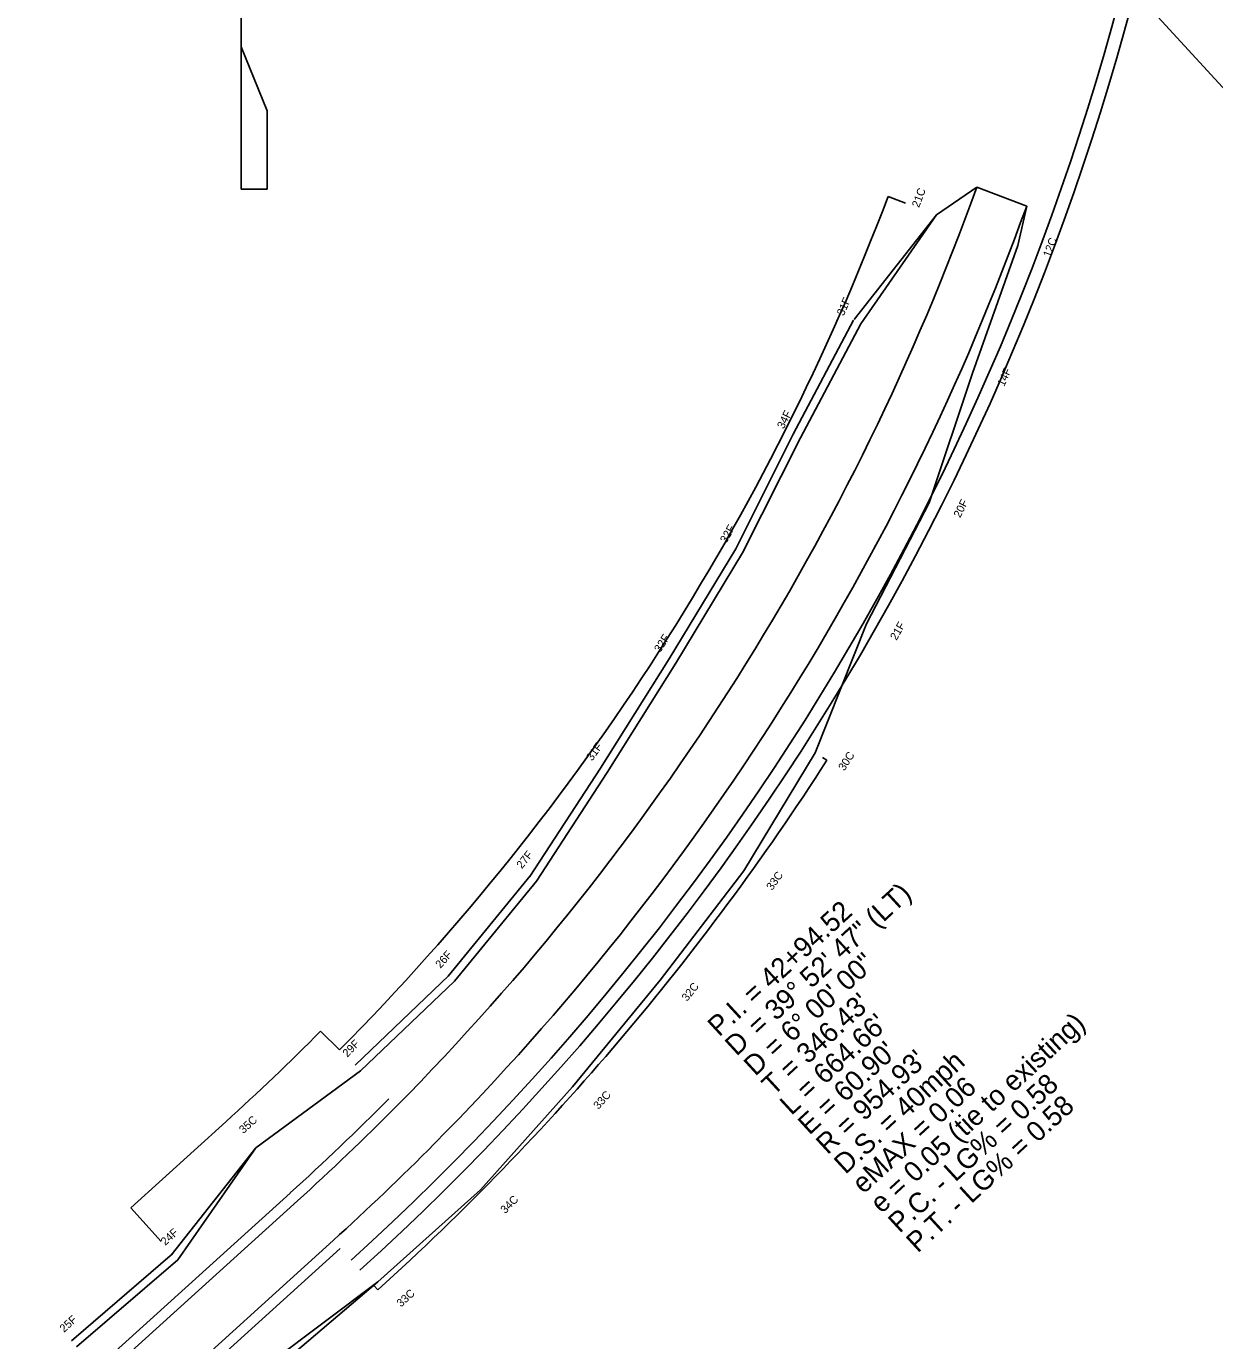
# Model space of a CAD drawing. Extents: x 2116464 to 2118397, y 979599 to 981222.
# Drawn here: x 2117628.4 to 2118074.1, y 980451.6 to 980944.4 of the extents above; entities that cross this region are included whole.
import ezdxf

# ---------------------------------------------------------------- set-up
doc = ezdxf.new("R2010")
doc.units = 0
for name, color, linetype in [('BR_GROUND LINES', 7, 'Continuous'), ('RD_EX_Misc', 7, 'Continuous'), ('RD_PD_CstnLmt', 7, 'Continuous'), ('RD_PD_CstnLmt_TX', 7, 'Continuous'), ('RD_PD_DR_ErosCtrl', 7, 'Continuous'), ('RD_PD_Final_TrvlWay', 7, 'Continuous'), ('RD_PD_GR', 7, 'Continuous'), ('RD_PD_RW', 7, 'Continuous'), ('RD_Sketch2', 7, 'Continuous')]:
    doc.layers.add(name, color=color, linetype=linetype)

msp = doc.modelspace()

# ---------------------------------------------------------------- linework, layer by layer
at = {"layer": 'RD_EX_Misc'}
for p, q in [((2117708.94, 980936.72), (2117708.94, 980991.12)), ((2117718.74, 980912.72), (2117708.94, 980936.72)), ((2117708.94, 980936.72), (2117708.94, 980883.31)), ((2117718.74, 980883.31), (2117718.74, 980912.99)), ((2117718.74, 980912.99), (2117718.74, 980912.72)), ((2117708.94, 980883.31), (2117718.74, 980883.31))]:
    msp.add_line(p, q, dxfattribs=at)
at = {"layer": 'RD_PD_CstnLmt'}
for p, q in [((2117969.75, 980873.73), (2117984.88, 980884.04)), ((2118000.26, 980862.18), (2118003.59, 980876.96)), ((2117941.36, 980832.8), (2117969.75, 980873.73)), ((2117983.25, 980814.38), (2118000.26, 980862.18)), ((2117918.71, 980790.09), (2117941.36, 980832.8)), ((2117967.03, 980765.75), (2117983.25, 980814.38)), ((2117897.04, 980746.94), (2117918.71, 980790.09)), ((2117943.47, 980720.42), (2117967.03, 980765.75)), ((2117872.03, 980705.62), (2117897.04, 980746.94)), ((2117924.27, 980672.04), (2117943.47, 980720.42)), ((2117846.31, 980664.65), (2117872.03, 980705.62)), ((2117897.55, 980627.77), (2117924.27, 980672.04)), ((2117819.75, 980623.93), (2117846.31, 980664.65)), ((2117866.1, 980586.74), (2117897.55, 980627.77)), ((2117788.97, 980586.31), (2117819.75, 980623.93)), ((2117753.78, 980552.75), (2117788.97, 980586.31)), ((2117833.3, 980546.76), (2117866.1, 980586.74)), ((2117714.55, 980523.86), (2117753.78, 980552.75)), ((2117798.79, 980508.16), (2117833.3, 980546.76)), ((2117685.2, 980481.88), (2117714.55, 980523.86)), ((2117760.21, 980473.62), (2117798.79, 980508.16)), ((2117647.26, 980449.29), (2117685.2, 980481.88)), ((2117720.02, 980443.41), (2117760.21, 980473.62))]:
    msp.add_line(p, q, dxfattribs=at)
for radius in [974.93, 979.93]:
    msp.add_arc((2117095.97, 981204.56), radius, 312.14821, 352.02781, dxfattribs=at)
at = {"layer": 'RD_PD_DR_ErosCtrl'}
for p, q in [((2117938.89, 980834.51), (2117969.75, 980873.73)), ((2117916.06, 980791.5), (2117938.7, 980834.21)), ((2117894.36, 980748.29), (2117916.03, 980791.44)), ((2117869.46, 980707.18), (2117894.48, 980748.5)), ((2117843.77, 980666.24), (2117869.49, 980707.22)), ((2117817.24, 980625.56), (2117843.79, 980666.28)), ((2117786.65, 980588.21), (2117817.43, 980625.83)), ((2117751.71, 980554.92), (2117786.9, 980588.48)), ((2117682.74, 980483.6), (2117714.55, 980523.86)), ((2117645.3, 980451.56), (2117683.24, 980484.16)), ((2117721.82, 980441.02), (2117760.21, 980473.62))]:
    msp.add_line(p, q, dxfattribs=at)
at = {"layer": 'RD_PD_Final_TrvlWay'}
for p, q in [((2118003.59, 980876.96), (2117984.88, 980884.04)), ((2117156.89, 979985.19), (2117730.06, 980503.98)), ((2117170.31, 979970.36), (2117743.49, 980489.15))]:
    msp.add_line(p, q, dxfattribs=at)
for radius, start, end in [(944.93, 315.26276, 340.17226), (964.93, 315.26276, 340.15341), (944.93, 312.14821, 315.26276), (964.93, 312.14821, 315.26276)]:
    msp.add_arc((2117095.97, 981204.56), radius, start, end, dxfattribs=at)
at = {"layer": 'RD_PD_GR'}
for p, q in [((2117472.27, 980276.04), (2117727.38, 980506.94)), ((2117746.17, 980486.18), (2117491.06, 980255.28))]:
    msp.add_line(p, q, dxfattribs=at)
msp.add_arc((2117095.97, 981204.56), 940.93, 312.14821, 315.26276, dxfattribs=at)
at = {"layer": 'RD_PD_RW'}
for p, q in [((2117951.62, 980880.6), (2117958.17, 980878.12)), ((2117926.98, 980670.3), (2117928.66, 980669.22)), ((2117738.78, 980567.62), (2117745.88, 980560.58)), ((2117667.57, 980501.36), (2117703.22, 980533.63)), ((2117667.57, 980501.36), (2117678.98, 980488.76)), ((2117760.26, 980470.61), (2117758.92, 980472.1))]:
    msp.add_line(p, q, dxfattribs=at)
for radius, start, end in [(914.93, 315.26276, 339.2627), (989.93, 312.14821, 327.26273), (904.93, 312.14821, 315.26276)]:
    msp.add_arc((2117095.97, 981204.56), radius, start, end, dxfattribs=at)
at = {"layer": 'RD_Sketch2'}
msp.add_lwpolyline([(2116741.06, 980247.26), (2117801.28, 981221.7), (2118396.78, 980573.79), (2117336.56, 979599.35)], close=True, dxfattribs=at)

# ---------------------------------------------------------------- texts
at = {"layer": 'BR_GROUND LINES'}
for s, p in [('    = 39%%d 52\' 47" (LT)', (2117895.02, 980557.87)), ('P.I. = 42+94.52', (2117888.25, 980565.23)), ('D = 6%%d 00\' 00"', (2117901.79, 980550.5)), ("T = 346.43'", (2117908.56, 980543.14)), ("L = 664.66'", (2117915.32, 980535.78)), ('e = 0.05 (tie to existing)', (2117949.16, 980498.96)), ('D', (2117894.75, 980558.01)), ("E = 60.90'", (2117922.09, 980528.41)), ("R = 954.93'", (2117928.86, 980521.05)), ('D.S. = 40mph', (2117935.62, 980513.69)), ('eMAX = 0.06', (2117942.39, 980506.33)), ('P.C. - LG% = 0.58', (2117955.92, 980491.6)), ('P.T. - LG% = 0.58', (2117962.69, 980484.24))]:
    msp.add_text(s, height=7.5, rotation=42.586, dxfattribs=at).set_placement(p)
at = {"layer": 'RD_PD_CstnLmt_TX'}
for s, rotation, p in [('21C', 69.2627, (2117963.2, 980876.21)), ('12C', 69.2627, (2118012.41, 980857.58)), ('31F', 66.2627, (2117934.95, 980835.62)), ('14F', 66.2627, (2117995.15, 980809.15)), ('34F', 63.2627, (2117912.46, 980793.24)), ('20F', 63.2627, (2117978.64, 980759.9)), ('32F', 60.2627, (2117890.97, 980750.41)), ('21F', 60.2627, (2117954.76, 980713.97)), ('32F', 57.2627, (2117866.14, 980709.41)), ('31F', 54.2627, (2117840.62, 980668.73)), ('30C', 57.2627, (2117935.21, 980665.01)), ('27F', 51.2627, (2117814.29, 980628.31)), ('33C', 54.2627, (2117908.11, 980620.18)), ('26F', 48.2628, (2117783.74, 980590.97)), ('32C', 51.2627, (2117876.24, 980578.61)), ('29F', 45.2628, (2117748.81, 980557.68)), ('33C', 48.2628, (2117843, 980538.1)), ('35C', 42.2628, (2117709.84, 980529.04)), ('34C', 45.2628, (2117808.02, 980499.01)), ('24F', 42.1482, (2117680.5, 980487.07)), ('33C', 42.2628, (2117768.95, 980463.99)), ('25F', 42.1482, (2117642.56, 980454.48))]:
    msp.add_text(s, height=3, rotation=rotation, dxfattribs=at).set_placement(p)

doc.saveas('drawing.dxf')
